// Mitsubishi GX Works2 project: 31.8个按钮单键启停(逻辑指令，未完成)   PLC: FX3U/FX3UC

PROGRAM MAIN
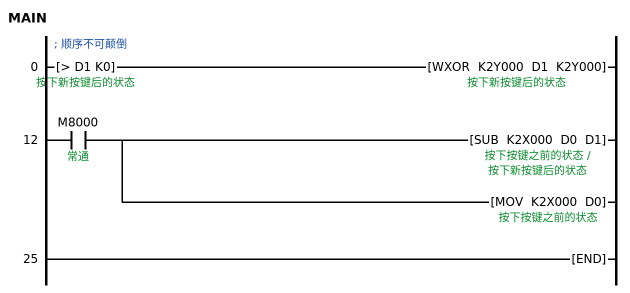
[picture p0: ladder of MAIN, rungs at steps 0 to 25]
; 顺序不可颠倒
0     LD>     D1 K0  ; 按下新按键后的状态
      WXOR    K2Y000 D1 K2Y000
        [note] 把K2Y0切换到D1状态
12    LD      M8000  ; 常通
      SUB     K2X000 D0 D1  ; 按下按键之前的状态
        [note] K2X0减按下按键之前的状态得到D1
      MOV     K2X000 D0
        [note] 记录按下按键前的状态
25    END
END_PROGRAM
